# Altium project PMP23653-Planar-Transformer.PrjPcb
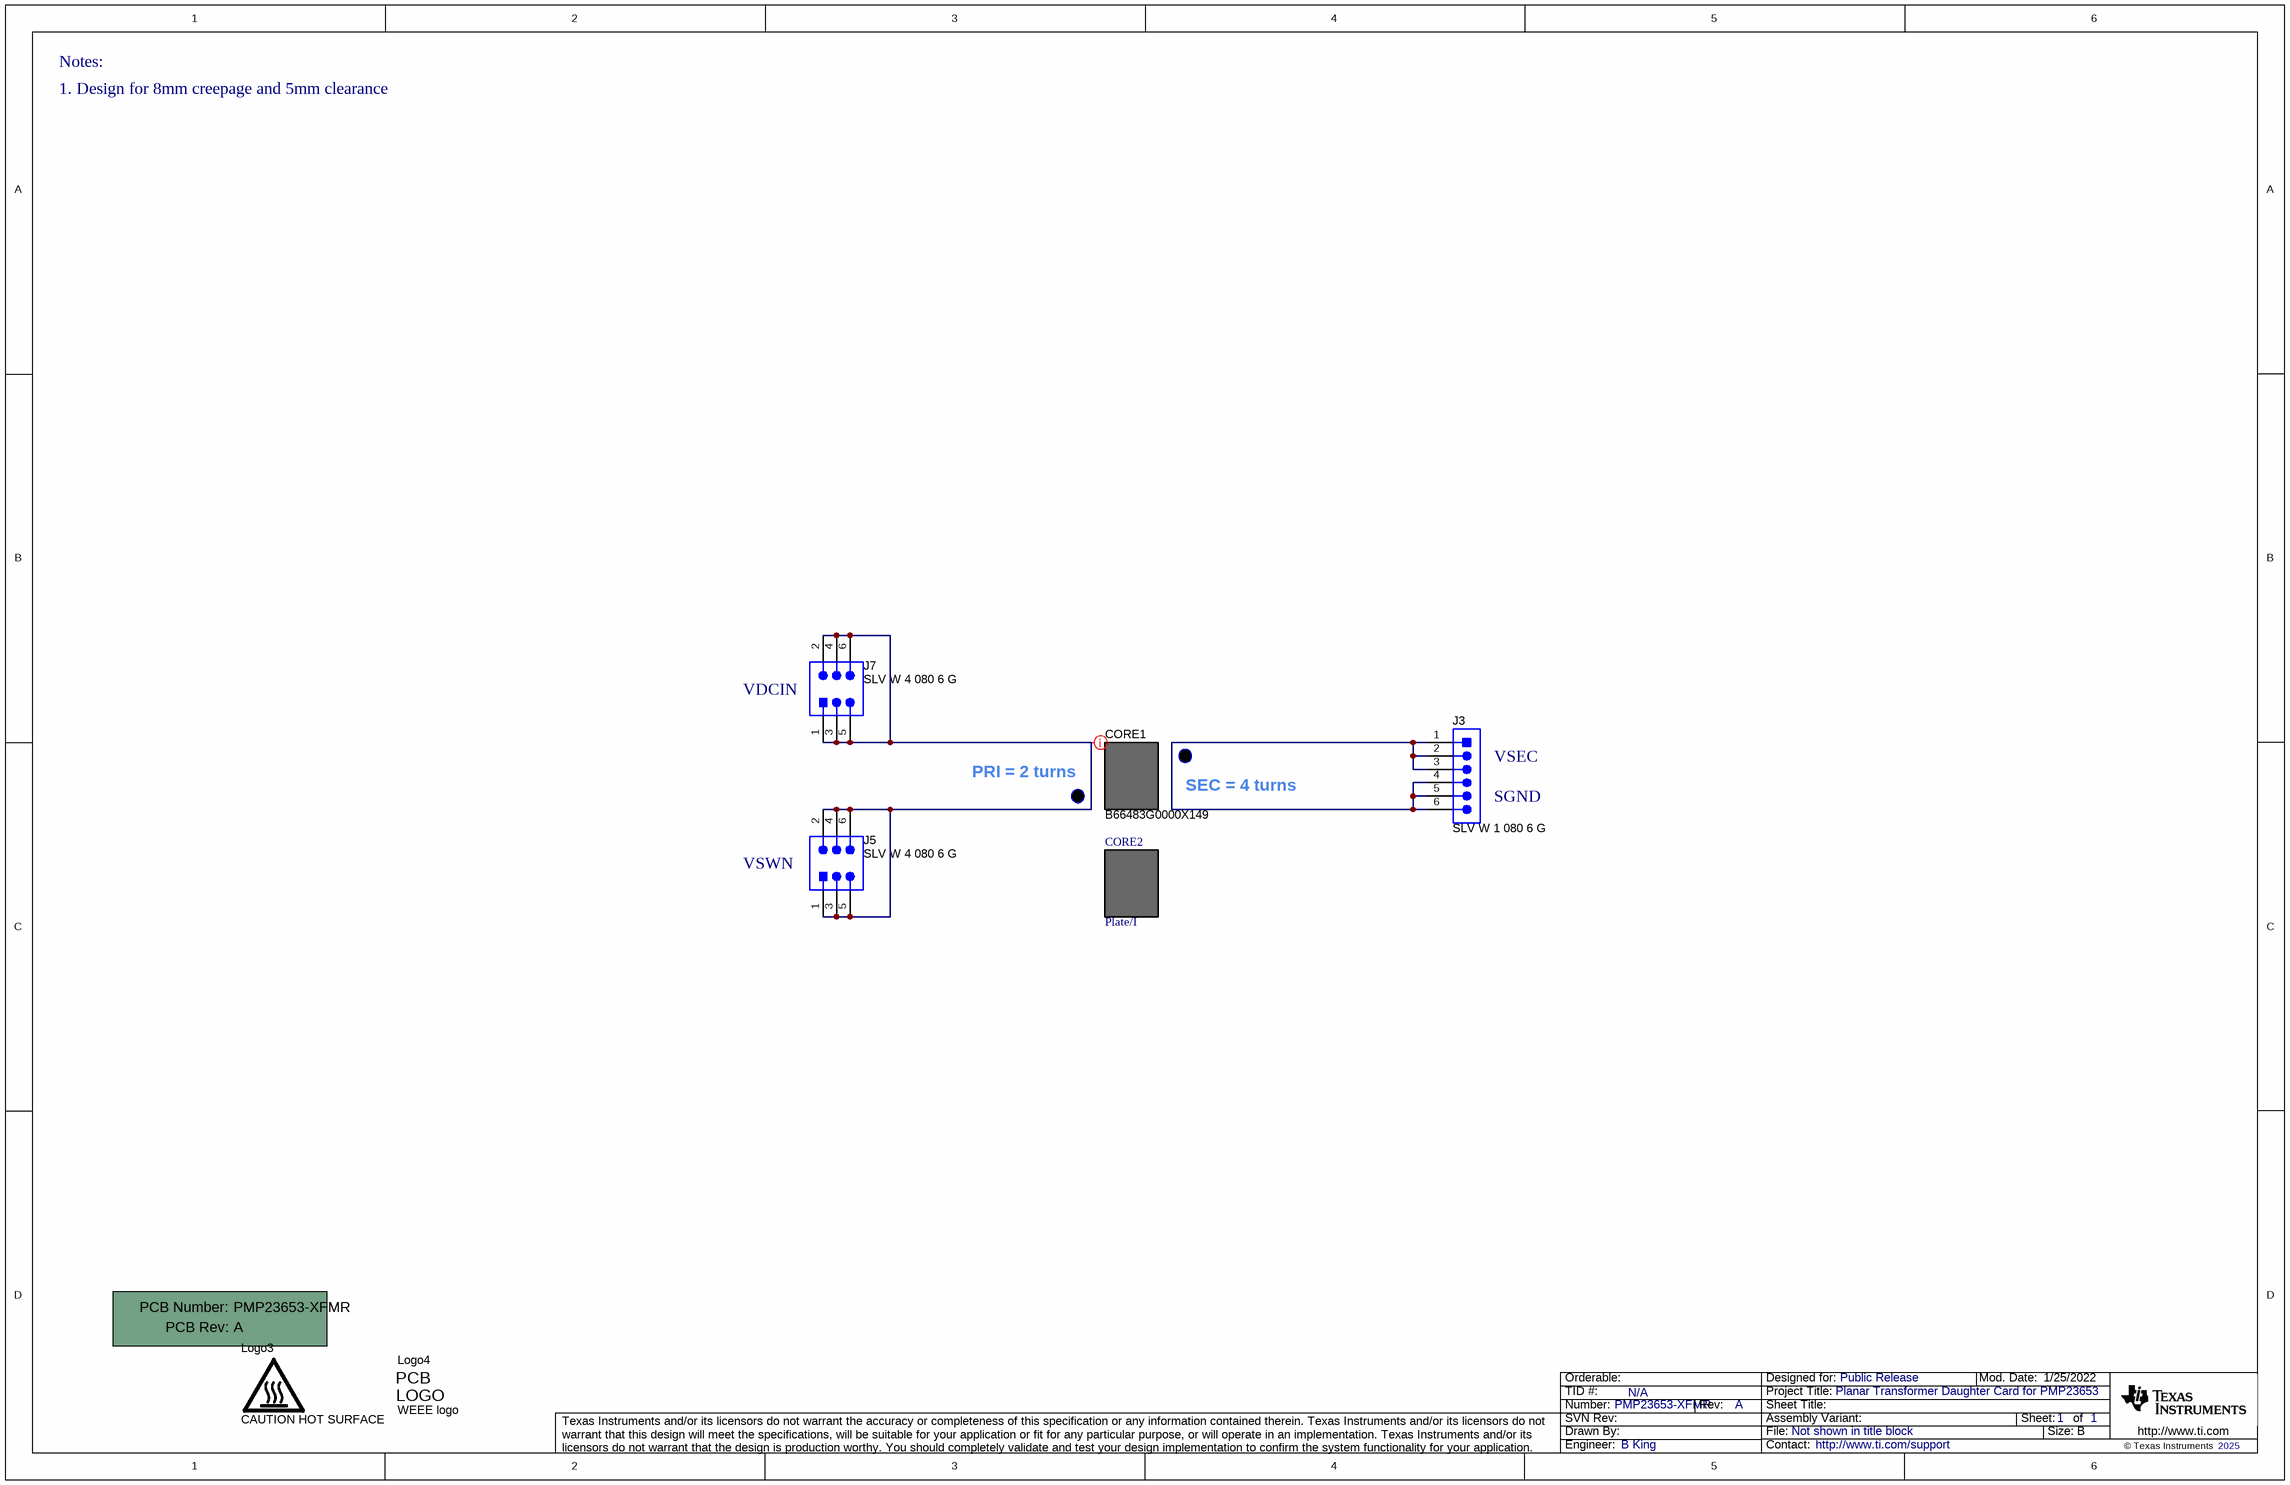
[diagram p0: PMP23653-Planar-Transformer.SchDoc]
CopyrightYear: 2025; PCB_Layout: B King; PCB_Rev: A; PRJ_Customer: Public Release; PRJ_Engineer: B King; PRJ_Number: PMP23653-XFMR; PRJ_Title: Planar Transformer Daughter Card for PMP23653; SCH_Rev: A; TechSupport: http://www.ti.com/support; TID: N/A
1 sheet, 8 parts. Net scope: global (net labels, ports and power ports of the same name join across sheets).
Board file: PMP23653-Planar-Transformer.PcbDoc

## Sheet PMP23653-Planar-Transformer.SchDoc
size 431 x 279 mm; Date: Not shown in title block; ApprovedBy: Not shown in title block; CheckedBy: Not shown in title block; Author: Not shown in title block; CompanyName: Not shown in title block; Engineer: Not shown in title block; Organization: Not shown in title block; Address1: Not shown in title block; Address2: Not shown in title block; Address3: Not shown in title block; Address4: Not shown in title block; DocumentNumber: 2; Revision: Use project parameter SCH_Rev; SheetNumber: 1; SheetTotal: 1; PageSetup: Record=PageOptions¦CenterHorizontal=True¦CenterVertical=True¦PrintScale=1.00¦XCorrection=1.00¦YCorrection=1.00¦PrintKind=0¦BorderSize=5000000¦LeftOffset=0¦BottomOffset=0¦Orientation=2¦PaperLength=1000¦PaperWidth=1000¦Scale=100¦PaperSource=15¦PrintQuality=600¦MediaType=1¦DitherType=10¦PaperKind=Letter¦PrintScaleMode=1

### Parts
!PCB1  Printed Circuit Board  (value not drawn)  (mechanical)
CORE1  B66483G0000X149  [PCBComponent_1]
CORE2  Plate/I  (mechanical)
J3  SLV W 1 080 6 G  [SLV W 1 080 6 G]
J5  SLV W 4 080 6 G  [SLV W 4 080 6 G]
J7  SLV W 4 080 6 G  [SLV W 4 080 6 G]
Logo3  CAUTION HOT SURFACE  [IEC_HotSurface_Small]  (no BOM)
Logo4  WEEE logo  [WEEE_Minimum]  (no BOM)

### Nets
NetJ3_1: J3.1 J3.2 J3.3 J3.4 J3.5 J3.6
NetJ5_1: J5.1 J5.2 J5.3 J5.4 J5.5 J5.6 J7.1 J7.2 J7.3 J7.4 J7.5 J7.6

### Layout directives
net class Primary: NetJ5_1

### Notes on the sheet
- Notes:
- 1. Design for 8mm creepage and 5mm clearance
- (near J7) VDCIN
- (near J3) VSEC
- PRI = 2 turns
- (near CORE1) SEC = 4 turns
- (near J3) SGND
- (near J5) VSWN

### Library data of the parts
!PCB1 = CMP-0003618-2: Manufacturer: Any; PartNumber: PMP23653-XFMR
CORE1 = EQ Core: EQ20 core set, N49 material, gapped to 1.1uH; Manufacturer: TDK; CompType: Used in some BOM reports.  Useful for finding later.
CORE2 = B66483K0000X149: I core set, N49 material, gapped to 1.1uH; Manufacturer: TDK; Manufacturer Lifecycle Status: PRODUCTION
J3 = SLV W 1 080 6 G: Connector Header Through Hole 6 position 0.050" (1.27mm)
J5 J7 = SLV W 4 080 6 G: Connector Header Through Hole 6 position 0.050" (1.27mm)
Logo3 = CMP-0074837-2: IEC 61010-1 Hot Surface Warning; Manufacturer: Texas Instruments; CompType: IC; AEC Category: Q200; SymbolCreator: a0412235
Logo4 = CMP-0074769-4: Manufacturer: Texas Instruments; CompType: IC; AEC Category: Q200

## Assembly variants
001: all parts fitted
